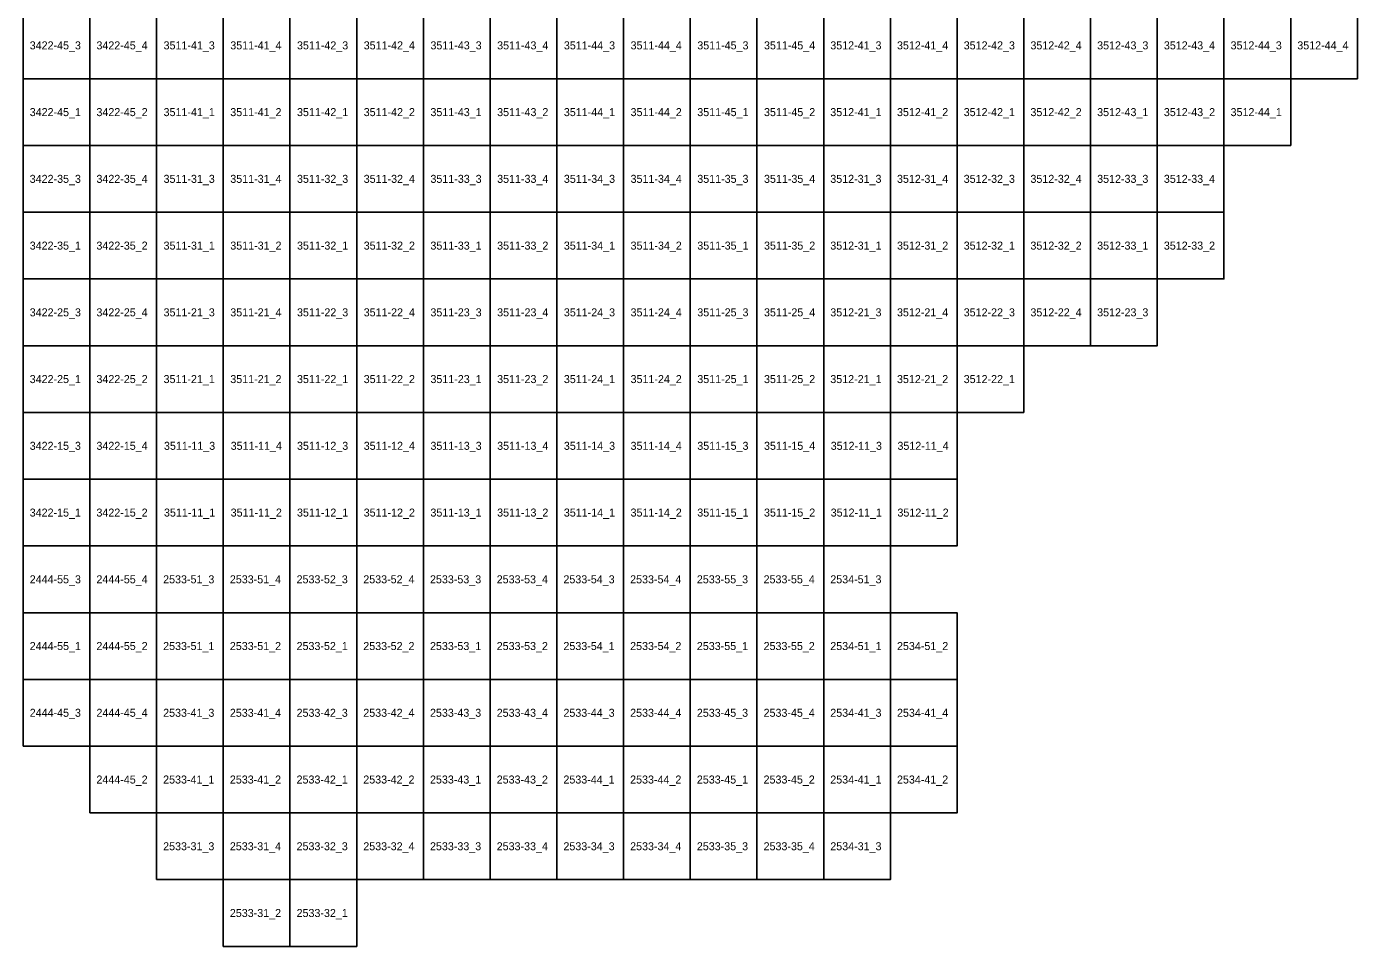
# Model space of a CAD drawing. Extents: x 312500 to 765000, y 172500 to 440000.
# Drawn here: x 695132 to 745000, y 185000 to 219452 of the extents above; entities that cross this region are included whole.
import ezdxf

# ---------------------------------------------------------------- set-up
doc = ezdxf.new("R2010")
doc.units = 0
doc.layers.add('Topo5_ramis_TKS2025', color=7, linetype='Continuous')
doc.layers.add('Topo5_ramis_TKS2025_Nr', color=7, linetype='Continuous')

msp = doc.modelspace()

# ---------------------------------------------------------------- linework, layer by layer
at = {"layer": 'Topo5_ramis_TKS2025'}
for points in [[(695000, 217500), (695000, 220000), (697500, 220000), (697500, 217500), (695000, 217500)], [(697500, 217500), (697500, 220000), (700000, 220000), (700000, 217500), (697500, 217500)], [(700000, 217500), (700000, 220000), (702500, 220000), (702500, 217500), (700000, 217500)], [(702500, 217500), (702500, 220000), (705000, 220000), (705000, 217500), (702500, 217500)], [(705000, 217500), (705000, 220000), (707500, 220000), (707500, 217500), (705000, 217500)], [(707500, 217500), (707500, 220000), (710000, 220000), (710000, 217500), (707500, 217500)], [(710000, 217500), (710000, 220000), (712500, 220000), (712500, 217500), (710000, 217500)], [(712500, 217500), (712500, 220000), (715000, 220000), (715000, 217500), (712500, 217500)], [(715000, 217500), (715000, 220000), (717500, 220000), (717500, 217500), (715000, 217500)], [(717500, 217500), (717500, 220000), (720000, 220000), (720000, 217500), (717500, 217500)], [(720000, 217500), (720000, 220000), (722500, 220000), (722500, 217500), (720000, 217500)], [(722500, 217500), (722500, 220000), (725000, 220000), (725000, 217500), (722500, 217500)], [(725000, 217500), (725000, 220000), (727500, 220000), (727500, 217500), (725000, 217500)], [(727500, 217500), (727500, 220000), (730000, 220000), (730000, 217500), (727500, 217500)], [(730000, 217500), (730000, 220000), (732500, 220000), (732500, 217500), (730000, 217500)], [(732500, 217500), (732500, 220000), (735000, 220000), (735000, 217500), (732500, 217500)], [(735000, 217500), (735000, 220000), (737500, 220000), (737500, 217500), (735000, 217500)], [(737500, 217500), (737500, 220000), (740000, 220000), (740000, 217500), (737500, 217500)], [(740000, 217500), (740000, 220000), (742500, 220000), (742500, 217500), (740000, 217500)], [(742500, 217500), (742500, 220000), (745000, 220000), (745000, 217500), (742500, 217500)], [(695000, 215000), (695000, 217500), (697500, 217500), (697500, 215000), (695000, 215000)], [(697500, 215000), (697500, 217500), (700000, 217500), (700000, 215000), (697500, 215000)], [(700000, 215000), (700000, 217500), (702500, 217500), (702500, 215000), (700000, 215000)], [(702500, 215000), (702500, 217500), (705000, 217500), (705000, 215000), (702500, 215000)], [(705000, 215000), (705000, 217500), (707500, 217500), (707500, 215000), (705000, 215000)], [(707500, 215000), (707500, 217500), (710000, 217500), (710000, 215000), (707500, 215000)], [(710000, 215000), (710000, 217500), (712500, 217500), (712500, 215000), (710000, 215000)], [(712500, 215000), (712500, 217500), (715000, 217500), (715000, 215000), (712500, 215000)], [(715000, 215000), (715000, 217500), (717500, 217500), (717500, 215000), (715000, 215000)], [(717500, 215000), (717500, 217500), (720000, 217500), (720000, 215000), (717500, 215000)], [(720000, 215000), (720000, 217500), (722500, 217500), (722500, 215000), (720000, 215000)], [(722500, 215000), (722500, 217500), (725000, 217500), (725000, 215000), (722500, 215000)], [(725000, 215000), (725000, 217500), (727500, 217500), (727500, 215000), (725000, 215000)], [(727500, 215000), (727500, 217500), (730000, 217500), (730000, 215000), (727500, 215000)], [(730000, 215000), (730000, 217500), (732500, 217500), (732500, 215000), (730000, 215000)], [(732500, 215000), (732500, 217500), (735000, 217500), (735000, 215000), (732500, 215000)], [(735000, 215000), (735000, 217500), (737500, 217500), (737500, 215000), (735000, 215000)], [(737500, 215000), (737500, 217500), (740000, 217500), (740000, 215000), (737500, 215000)], [(740000, 215000), (740000, 217500), (742500, 217500), (742500, 215000), (740000, 215000)], [(695000, 212500), (695000, 215000), (697500, 215000), (697500, 212500), (695000, 212500)], [(697500, 212500), (697500, 215000), (700000, 215000), (700000, 212500), (697500, 212500)], [(700000, 212500), (700000, 215000), (702500, 215000), (702500, 212500), (700000, 212500)], [(702500, 212500), (702500, 215000), (705000, 215000), (705000, 212500), (702500, 212500)], [(705000, 212500), (705000, 215000), (707500, 215000), (707500, 212500), (705000, 212500)], [(707500, 212500), (707500, 215000), (710000, 215000), (710000, 212500), (707500, 212500)], [(710000, 212500), (710000, 215000), (712500, 215000), (712500, 212500), (710000, 212500)], [(712500, 212500), (712500, 215000), (715000, 215000), (715000, 212500), (712500, 212500)], [(715000, 212500), (715000, 215000), (717500, 215000), (717500, 212500), (715000, 212500)], [(717500, 212500), (717500, 215000), (720000, 215000), (720000, 212500), (717500, 212500)], [(720000, 212500), (720000, 215000), (722500, 215000), (722500, 212500), (720000, 212500)], [(722500, 212500), (722500, 215000), (725000, 215000), (725000, 212500), (722500, 212500)], [(725000, 212500), (725000, 215000), (727500, 215000), (727500, 212500), (725000, 212500)], [(727500, 212500), (727500, 215000), (730000, 215000), (730000, 212500), (727500, 212500)], [(730000, 212500), (730000, 215000), (732500, 215000), (732500, 212500), (730000, 212500)], [(732500, 212500), (732500, 215000), (735000, 215000), (735000, 212500), (732500, 212500)], [(735000, 212500), (735000, 215000), (737500, 215000), (737500, 212500), (735000, 212500)], [(737500, 212500), (737500, 215000), (740000, 215000), (740000, 212500), (737500, 212500)], [(695000, 210000), (695000, 212500), (697500, 212500), (697500, 210000), (695000, 210000)], [(697500, 210000), (697500, 212500), (700000, 212500), (700000, 210000), (697500, 210000)], [(700000, 210000), (700000, 212500), (702500, 212500), (702500, 210000), (700000, 210000)], [(702500, 210000), (702500, 212500), (705000, 212500), (705000, 210000), (702500, 210000)], [(705000, 210000), (705000, 212500), (707500, 212500), (707500, 210000), (705000, 210000)], [(707500, 210000), (707500, 212500), (710000, 212500), (710000, 210000), (707500, 210000)], [(710000, 210000), (710000, 212500), (712500, 212500), (712500, 210000), (710000, 210000)], [(712500, 210000), (712500, 212500), (715000, 212500), (715000, 210000), (712500, 210000)], [(715000, 210000), (715000, 212500), (717500, 212500), (717500, 210000), (715000, 210000)], [(717500, 210000), (717500, 212500), (720000, 212500), (720000, 210000), (717500, 210000)], [(720000, 210000), (720000, 212500), (722500, 212500), (722500, 210000), (720000, 210000)], [(722500, 210000), (722500, 212500), (725000, 212500), (725000, 210000), (722500, 210000)], [(725000, 210000), (725000, 212500), (727500, 212500), (727500, 210000), (725000, 210000)], [(727500, 210000), (727500, 212500), (730000, 212500), (730000, 210000), (727500, 210000)], [(730000, 210000), (730000, 212500), (732500, 212500), (732500, 210000), (730000, 210000)], [(732500, 210000), (732500, 212500), (735000, 212500), (735000, 210000), (732500, 210000)], [(735000, 210000), (735000, 212500), (737500, 212500), (737500, 210000), (735000, 210000)], [(737500, 210000), (737500, 212500), (740000, 212500), (740000, 210000), (737500, 210000)], [(695000, 207500), (695000, 210000), (697500, 210000), (697500, 207500), (695000, 207500)], [(697500, 207500), (697500, 210000), (700000, 210000), (700000, 207500), (697500, 207500)], [(700000, 207500), (700000, 210000), (702500, 210000), (702500, 207500), (700000, 207500)], [(702500, 207500), (702500, 210000), (705000, 210000), (705000, 207500), (702500, 207500)], [(705000, 207500), (705000, 210000), (707500, 210000), (707500, 207500), (705000, 207500)], [(707500, 207500), (707500, 210000), (710000, 210000), (710000, 207500), (707500, 207500)], [(710000, 207500), (710000, 210000), (712500, 210000), (712500, 207500), (710000, 207500)], [(712500, 207500), (712500, 210000), (715000, 210000), (715000, 207500), (712500, 207500)], [(715000, 207500), (715000, 210000), (717500, 210000), (717500, 207500), (715000, 207500)], [(717500, 207500), (717500, 210000), (720000, 210000), (720000, 207500), (717500, 207500)], [(720000, 207500), (720000, 210000), (722500, 210000), (722500, 207500), (720000, 207500)], [(722500, 207500), (722500, 210000), (725000, 210000), (725000, 207500), (722500, 207500)], [(725000, 207500), (725000, 210000), (727500, 210000), (727500, 207500), (725000, 207500)], [(727500, 207500), (727500, 210000), (730000, 210000), (730000, 207500), (727500, 207500)], [(730000, 207500), (730000, 210000), (732500, 210000), (732500, 207500), (730000, 207500)], [(732500, 207500), (732500, 210000), (735000, 210000), (735000, 207500), (732500, 207500)], [(735000, 207500), (735000, 210000), (737500, 210000), (737500, 207500), (735000, 207500)], [(695000, 205000), (695000, 207500), (697500, 207500), (697500, 205000), (695000, 205000)], [(697500, 205000), (697500, 207500), (700000, 207500), (700000, 205000), (697500, 205000)], [(700000, 205000), (700000, 207500), (702500, 207500), (702500, 205000), (700000, 205000)], [(702500, 205000), (702500, 207500), (705000, 207500), (705000, 205000), (702500, 205000)], [(705000, 205000), (705000, 207500), (707500, 207500), (707500, 205000), (705000, 205000)], [(707500, 205000), (707500, 207500), (710000, 207500), (710000, 205000), (707500, 205000)], [(710000, 205000), (710000, 207500), (712500, 207500), (712500, 205000), (710000, 205000)], [(712500, 205000), (712500, 207500), (715000, 207500), (715000, 205000), (712500, 205000)], [(715000, 205000), (715000, 207500), (717500, 207500), (717500, 205000), (715000, 205000)], [(717500, 205000), (717500, 207500), (720000, 207500), (720000, 205000), (717500, 205000)], [(720000, 205000), (720000, 207500), (722500, 207500), (722500, 205000), (720000, 205000)], [(722500, 205000), (722500, 207500), (725000, 207500), (725000, 205000), (722500, 205000)], [(725000, 205000), (725000, 207500), (727500, 207500), (727500, 205000), (725000, 205000)], [(727500, 205000), (727500, 207500), (730000, 207500), (730000, 205000), (727500, 205000)], [(730000, 205000), (730000, 207500), (732500, 207500), (732500, 205000), (730000, 205000)], [(695000, 202500), (695000, 205000), (697500, 205000), (697500, 202500), (695000, 202500)], [(697500, 202500), (697500, 205000), (700000, 205000), (700000, 202500), (697500, 202500)], [(700000, 202500), (700000, 205000), (702500, 205000), (702500, 202500), (700000, 202500)], [(702500, 202500), (702500, 205000), (705000, 205000), (705000, 202500), (702500, 202500)], [(705000, 202500), (705000, 205000), (707500, 205000), (707500, 202500), (705000, 202500)], [(707500, 202500), (707500, 205000), (710000, 205000), (710000, 202500), (707500, 202500)], [(710000, 202500), (710000, 205000), (712500, 205000), (712500, 202500), (710000, 202500)], [(712500, 202500), (712500, 205000), (715000, 205000), (715000, 202500), (712500, 202500)], [(715000, 202500), (715000, 205000), (717500, 205000), (717500, 202500), (715000, 202500)], [(717500, 202500), (717500, 205000), (720000, 205000), (720000, 202500), (717500, 202500)], [(720000, 202500), (720000, 205000), (722500, 205000), (722500, 202500), (720000, 202500)], [(722500, 202500), (722500, 205000), (725000, 205000), (725000, 202500), (722500, 202500)], [(725000, 202500), (725000, 205000), (727500, 205000), (727500, 202500), (725000, 202500)], [(727500, 202500), (727500, 205000), (730000, 205000), (730000, 202500), (727500, 202500)], [(695000, 200000), (695000, 202500), (697500, 202500), (697500, 200000), (695000, 200000)], [(697500, 200000), (697500, 202500), (700000, 202500), (700000, 200000), (697500, 200000)], [(700000, 200000), (700000, 202500), (702500, 202500), (702500, 200000), (700000, 200000)], [(702500, 200000), (702500, 202500), (705000, 202500), (705000, 200000), (702500, 200000)], [(705000, 200000), (705000, 202500), (707500, 202500), (707500, 200000), (705000, 200000)], [(707500, 200000), (707500, 202500), (710000, 202500), (710000, 200000), (707500, 200000)], [(710000, 200000), (710000, 202500), (712500, 202500), (712500, 200000), (710000, 200000)], [(712500, 200000), (712500, 202500), (715000, 202500), (715000, 200000), (712500, 200000)], [(715000, 200000), (715000, 202500), (717500, 202500), (717500, 200000), (715000, 200000)], [(717500, 200000), (717500, 202500), (720000, 202500), (720000, 200000), (717500, 200000)], [(720000, 200000), (720000, 202500), (722500, 202500), (722500, 200000), (720000, 200000)], [(722500, 200000), (722500, 202500), (725000, 202500), (725000, 200000), (722500, 200000)], [(725000, 200000), (725000, 202500), (727500, 202500), (727500, 200000), (725000, 200000)], [(727500, 200000), (727500, 202500), (730000, 202500), (730000, 200000), (727500, 200000)], [(695000, 197500), (695000, 200000), (697500, 200000), (697500, 197500), (695000, 197500)], [(697500, 197500), (697500, 200000), (700000, 200000), (700000, 197500), (697500, 197500)], [(700000, 197500), (700000, 200000), (702500, 200000), (702500, 197500), (700000, 197500)], [(702500, 197500), (702500, 200000), (705000, 200000), (705000, 197500), (702500, 197500)], [(705000, 197500), (705000, 200000), (707500, 200000), (707500, 197500), (705000, 197500)], [(707500, 197500), (707500, 200000), (710000, 200000), (710000, 197500), (707500, 197500)], [(710000, 197500), (710000, 200000), (712500, 200000), (712500, 197500), (710000, 197500)], [(712500, 197500), (712500, 200000), (715000, 200000), (715000, 197500), (712500, 197500)], [(715000, 197500), (715000, 200000), (717500, 200000), (717500, 197500), (715000, 197500)], [(717500, 197500), (717500, 200000), (720000, 200000), (720000, 197500), (717500, 197500)], [(720000, 197500), (720000, 200000), (722500, 200000), (722500, 197500), (720000, 197500)], [(722500, 197500), (722500, 200000), (725000, 200000), (725000, 197500), (722500, 197500)], [(725000, 197500), (725000, 200000), (727500, 200000), (727500, 197500), (725000, 197500)], [(695000, 195000), (695000, 197500), (697500, 197500), (697500, 195000), (695000, 195000)], [(697500, 195000), (697500, 197500), (700000, 197500), (700000, 195000), (697500, 195000)], [(700000, 195000), (700000, 197500), (702500, 197500), (702500, 195000), (700000, 195000)], [(702500, 195000), (702500, 197500), (705000, 197500), (705000, 195000), (702500, 195000)], [(705000, 195000), (705000, 197500), (707500, 197500), (707500, 195000), (705000, 195000)], [(707500, 195000), (707500, 197500), (710000, 197500), (710000, 195000), (707500, 195000)], [(710000, 195000), (710000, 197500), (712500, 197500), (712500, 195000), (710000, 195000)], [(712500, 195000), (712500, 197500), (715000, 197500), (715000, 195000), (712500, 195000)], [(715000, 195000), (715000, 197500), (717500, 197500), (717500, 195000), (715000, 195000)], [(717500, 195000), (717500, 197500), (720000, 197500), (720000, 195000), (717500, 195000)], [(720000, 195000), (720000, 197500), (722500, 197500), (722500, 195000), (720000, 195000)], [(722500, 195000), (722500, 197500), (725000, 197500), (725000, 195000), (722500, 195000)], [(725000, 195000), (725000, 197500), (727500, 197500), (727500, 195000), (725000, 195000)], [(727500, 195000), (727500, 197500), (730000, 197500), (730000, 195000), (727500, 195000)], [(695000, 192500), (695000, 195000), (697500, 195000), (697500, 192500), (695000, 192500)], [(697500, 192500), (697500, 195000), (700000, 195000), (700000, 192500), (697500, 192500)], [(700000, 192500), (700000, 195000), (702500, 195000), (702500, 192500), (700000, 192500)], [(702500, 192500), (702500, 195000), (705000, 195000), (705000, 192500), (702500, 192500)], [(705000, 192500), (705000, 195000), (707500, 195000), (707500, 192500), (705000, 192500)], [(707500, 192500), (707500, 195000), (710000, 195000), (710000, 192500), (707500, 192500)], [(710000, 192500), (710000, 195000), (712500, 195000), (712500, 192500), (710000, 192500)], [(712500, 192500), (712500, 195000), (715000, 195000), (715000, 192500), (712500, 192500)], [(715000, 192500), (715000, 195000), (717500, 195000), (717500, 192500), (715000, 192500)], [(717500, 192500), (717500, 195000), (720000, 195000), (720000, 192500), (717500, 192500)], [(720000, 192500), (720000, 195000), (722500, 195000), (722500, 192500), (720000, 192500)], [(722500, 192500), (722500, 195000), (725000, 195000), (725000, 192500), (722500, 192500)], [(725000, 192500), (725000, 195000), (727500, 195000), (727500, 192500), (725000, 192500)], [(727500, 192500), (727500, 195000), (730000, 195000), (730000, 192500), (727500, 192500)], [(697500, 190000), (697500, 192500), (700000, 192500), (700000, 190000), (697500, 190000)], [(700000, 190000), (700000, 192500), (702500, 192500), (702500, 190000), (700000, 190000)], [(702500, 190000), (702500, 192500), (705000, 192500), (705000, 190000), (702500, 190000)], [(705000, 190000), (705000, 192500), (707500, 192500), (707500, 190000), (705000, 190000)], [(707500, 190000), (707500, 192500), (710000, 192500), (710000, 190000), (707500, 190000)], [(710000, 190000), (710000, 192500), (712500, 192500), (712500, 190000), (710000, 190000)], [(712500, 190000), (712500, 192500), (715000, 192500), (715000, 190000), (712500, 190000)], [(715000, 190000), (715000, 192500), (717500, 192500), (717500, 190000), (715000, 190000)], [(717500, 190000), (717500, 192500), (720000, 192500), (720000, 190000), (717500, 190000)], [(720000, 190000), (720000, 192500), (722500, 192500), (722500, 190000), (720000, 190000)], [(722500, 190000), (722500, 192500), (725000, 192500), (725000, 190000), (722500, 190000)], [(725000, 190000), (725000, 192500), (727500, 192500), (727500, 190000), (725000, 190000)], [(727500, 190000), (727500, 192500), (730000, 192500), (730000, 190000), (727500, 190000)], [(700000, 187500), (700000, 190000), (702500, 190000), (702500, 187500), (700000, 187500)], [(702500, 187500), (702500, 190000), (705000, 190000), (705000, 187500), (702500, 187500)], [(705000, 187500), (705000, 190000), (707500, 190000), (707500, 187500), (705000, 187500)], [(707500, 187500), (707500, 190000), (710000, 190000), (710000, 187500), (707500, 187500)], [(710000, 187500), (710000, 190000), (712500, 190000), (712500, 187500), (710000, 187500)], [(712500, 187500), (712500, 190000), (715000, 190000), (715000, 187500), (712500, 187500)], [(715000, 187500), (715000, 190000), (717500, 190000), (717500, 187500), (715000, 187500)], [(717500, 187500), (717500, 190000), (720000, 190000), (720000, 187500), (717500, 187500)], [(720000, 187500), (720000, 190000), (722500, 190000), (722500, 187500), (720000, 187500)], [(722500, 187500), (722500, 190000), (725000, 190000), (725000, 187500), (722500, 187500)], [(725000, 187500), (725000, 190000), (727500, 190000), (727500, 187500), (725000, 187500)], [(702500, 185000), (702500, 187500), (705000, 187500), (705000, 185000), (702500, 185000)], [(705000, 185000), (705000, 187500), (707500, 187500), (707500, 185000), (705000, 185000)]]:
    msp.add_lwpolyline(points, dxfattribs=at)

# ---------------------------------------------------------------- texts
at = {"layer": 'Topo5_ramis_TKS2025_Nr'}
for s, p in [('3422-45_3', (695248, 218600)), ('3422-45_4', (697748, 218600)), ('3511-41_3', (700264, 218600)), ('3511-41_4', (702764, 218600)), ('3511-42_3', (705264, 218600)), ('3511-42_4', (707764, 218600)), ('3511-43_3', (710264, 218600)), ('3511-43_4', (712764, 218600)), ('3511-44_3', (715264, 218600)), ('3511-44_4', (717764, 218600)), ('3511-45_3', (720264, 218600)), ('3511-45_4', (722764, 218600)), ('3512-41_3', (725248, 218600)), ('3512-41_4', (727748, 218600)), ('3512-42_3', (730248, 218600)), ('3512-42_4', (732748, 218600)), ('3512-43_3', (735248, 218600)), ('3512-43_4', (737748, 218600)), ('3512-44_3', (740248, 218600)), ('3512-44_4', (742748, 218600)), ('3422-45_1', (695248, 216100)), ('3422-45_2', (697748, 216100)), ('3511-41_1', (700264, 216100)), ('3511-41_2', (702764, 216100)), ('3511-42_1', (705264, 216100)), ('3511-42_2', (707764, 216100)), ('3511-43_1', (710264, 216100)), ('3511-43_2', (712764, 216100)), ('3511-44_1', (715264, 216100)), ('3511-44_2', (717764, 216100)), ('3511-45_1', (720264, 216100)), ('3511-45_2', (722764, 216100)), ('3512-41_1', (725248, 216100)), ('3512-41_2', (727748, 216100)), ('3512-42_1', (730248, 216100)), ('3512-42_2', (732748, 216100)), ('3512-43_1', (735248, 216100)), ('3512-43_2', (737748, 216100)), ('3512-44_1', (740248, 216100)), ('3422-35_3', (695248, 213600)), ('3422-35_4', (697748, 213600)), ('3511-31_3', (700264, 213600)), ('3511-31_4', (702764, 213600)), ('3511-32_3', (705264, 213600)), ('3511-32_4', (707764, 213600)), ('3511-33_3', (710264, 213600)), ('3511-33_4', (712764, 213600)), ('3511-34_3', (715264, 213600)), ('3511-34_4', (717764, 213600)), ('3511-35_3', (720264, 213600)), ('3511-35_4', (722764, 213600)), ('3512-31_3', (725248, 213600)), ('3512-31_4', (727748, 213600)), ('3512-32_3', (730248, 213600)), ('3512-32_4', (732748, 213600)), ('3512-33_3', (735248, 213600)), ('3512-33_4', (737748, 213600)), ('3422-35_1', (695248, 211100)), ('3422-35_2', (697748, 211100)), ('3511-31_1', (700264, 211100)), ('3511-31_2', (702764, 211100)), ('3511-32_1', (705264, 211100)), ('3511-32_2', (707764, 211100)), ('3511-33_1', (710264, 211100)), ('3511-33_2', (712764, 211100)), ('3511-34_1', (715264, 211100)), ('3511-34_2', (717764, 211100)), ('3511-35_1', (720264, 211100)), ('3511-35_2', (722764, 211100)), ('3512-31_1', (725248, 211100)), ('3512-31_2', (727748, 211100)), ('3512-32_1', (730248, 211100)), ('3512-32_2', (732748, 211100)), ('3512-33_1', (735248, 211100)), ('3512-33_2', (737748, 211100)), ('3422-25_3', (695248, 208600)), ('3422-25_4', (697748, 208600)), ('3511-21_3', (700264, 208600)), ('3511-21_4', (702764, 208600)), ('3511-22_3', (705264, 208600)), ('3511-22_4', (707764, 208600)), ('3511-23_3', (710264, 208600)), ('3511-23_4', (712764, 208600)), ('3511-24_3', (715264, 208600)), ('3511-24_4', (717764, 208600)), ('3511-25_3', (720264, 208600)), ('3511-25_4', (722764, 208600)), ('3512-21_3', (725248, 208600)), ('3512-21_4', (727748, 208600)), ('3512-22_3', (730248, 208600)), ('3512-22_4', (732748, 208600)), ('3512-23_3', (735248, 208600)), ('3422-25_1', (695248, 206100)), ('3422-25_2', (697748, 206100)), ('3511-21_1', (700264, 206100)), ('3511-21_2', (702764, 206100)), ('3511-22_1', (705264, 206100)), ('3511-22_2', (707764, 206100)), ('3511-23_1', (710264, 206100)), ('3511-23_2', (712764, 206100)), ('3511-24_1', (715264, 206100)), ('3511-24_2', (717764, 206100)), ('3511-25_1', (720264, 206100)), ('3511-25_2', (722764, 206100)), ('3512-21_1', (725248, 206100)), ('3512-21_2', (727748, 206100)), ('3512-22_1', (730248, 206100)), ('3422-15_3', (695248, 203600)), ('3422-15_4', (697748, 203600)), ('3511-11_3', (700279, 203600)), ('3511-11_4', (702779, 203600)), ('3511-12_3', (705264, 203600)), ('3511-12_4', (707764, 203600)), ('3511-13_3', (710264, 203600)), ('3511-13_4', (712764, 203600)), ('3511-14_3', (715264, 203600)), ('3511-14_4', (717764, 203600)), ('3511-15_3', (720264, 203600)), ('3511-15_4', (722764, 203600)), ('3512-11_3', (725264, 203600)), ('3512-11_4', (727764, 203600)), ('3422-15_1', (695248, 201100)), ('3422-15_2', (697748, 201100)), ('3511-11_1', (700279, 201100)), ('3511-11_2', (702779, 201100)), ('3511-12_1', (705264, 201100)), ('3511-12_2', (707764, 201100)), ('3511-13_1', (710264, 201100)), ('3511-13_2', (712764, 201100)), ('3511-14_1', (715264, 201100)), ('3511-14_2', (717764, 201100)), ('3511-15_1', (720264, 201100)), ('3511-15_2', (722764, 201100)), ('3512-11_1', (725264, 201100)), ('3512-11_2', (727764, 201100)), ('2444-55_3', (695248, 198600)), ('2444-55_4', (697748, 198600)), ('2533-51_3', (700248, 198600)), ('2533-51_4', (702748, 198600)), ('2533-52_3', (705248, 198600)), ('2533-52_4', (707748, 198600)), ('2533-53_3', (710248, 198600)), ('2533-53_4', (712748, 198600)), ('2533-54_3', (715248, 198600)), ('2533-54_4', (717748, 198600)), ('2533-55_3', (720248, 198600)), ('2533-55_4', (722748, 198600)), ('2534-51_3', (725248, 198600)), ('2444-55_1', (695248, 196100)), ('2444-55_2', (697748, 196100)), ('2533-51_1', (700248, 196100)), ('2533-51_2', (702748, 196100)), ('2533-52_1', (705248, 196100)), ('2533-52_2', (707748, 196100)), ('2533-53_1', (710248, 196100)), ('2533-53_2', (712748, 196100)), ('2533-54_1', (715248, 196100)), ('2533-54_2', (717748, 196100)), ('2533-55_1', (720248, 196100)), ('2533-55_2', (722748, 196100)), ('2534-51_1', (725248, 196100)), ('2534-51_2', (727748, 196100)), ('2444-45_3', (695248, 193600)), ('2444-45_4', (697748, 193600)), ('2533-41_3', (700248, 193600)), ('2533-41_4', (702748, 193600)), ('2533-42_3', (705248, 193600)), ('2533-42_4', (707748, 193600)), ('2533-43_3', (710248, 193600)), ('2533-43_4', (712748, 193600)), ('2533-44_3', (715248, 193600)), ('2533-44_4', (717748, 193600)), ('2533-45_3', (720248, 193600)), ('2533-45_4', (722748, 193600)), ('2534-41_3', (725248, 193600)), ('2534-41_4', (727748, 193600)), ('2444-45_2', (697748, 191100)), ('2533-41_1', (700248, 191100)), ('2533-41_2', (702748, 191100)), ('2533-42_1', (705248, 191100)), ('2533-42_2', (707748, 191100)), ('2533-43_1', (710248, 191100)), ('2533-43_2', (712748, 191100)), ('2533-44_1', (715248, 191100)), ('2533-44_2', (717748, 191100)), ('2533-45_1', (720248, 191100)), ('2533-45_2', (722748, 191100)), ('2534-41_1', (725248, 191100)), ('2534-41_2', (727748, 191100)), ('2533-31_3', (700248, 188600)), ('2533-31_4', (702748, 188600)), ('2533-32_3', (705248, 188600)), ('2533-32_4', (707748, 188600)), ('2533-33_3', (710248, 188600)), ('2533-33_4', (712748, 188600)), ('2533-34_3', (715248, 188600)), ('2533-34_4', (717748, 188600)), ('2533-35_3', (720248, 188600)), ('2533-35_4', (722748, 188600)), ('2534-31_3', (725248, 188600)), ('2533-31_2', (702748, 186100)), ('2533-32_1', (705248, 186100))]:
    msp.add_text(s, height=300, dxfattribs=at).set_placement(p)

doc.saveas('drawing.dxf')
